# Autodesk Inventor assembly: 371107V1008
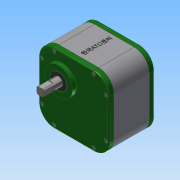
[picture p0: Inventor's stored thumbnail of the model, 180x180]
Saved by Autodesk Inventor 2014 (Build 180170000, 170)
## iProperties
Created: 2017-11
Part Number: 371107V1008
Document SubType Name: Assembly
Designer: NET
Mass: 1902.4 g
Surface Area: 2353.72 cm^2
Volume: 854.265 cm^3
Density: 2.22695 g/cm^3
Author: NET
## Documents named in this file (11)
- C:\Users\NET\Desktop\371107V1008\371107V1008.iam
- C:\Users\NET\Desktop\371107V1008\본체.ipt
- C:\Users\NET\Desktop\371107V1008\뒤커버.ipt
- C:\Users\NET\Desktop\371107V1008\메인축.ipt
- C:\Users\NET\Desktop\371107V1008\베어링 608.ipt
- C:\Users\NET\Desktop\371107V1008\베어링 6003.ipt
- C:\Users\NET\Desktop\371107V1008\볼트 M4.ipt
- C:\Users\NET\Desktop\371107V1008\서브축.ipt
- C:\Users\NET\Desktop\371107V1008\앞커버.ipt
- C:\Users\NET\Desktop\371107V1008\오일실 8 22 7.ipt
- C:\Users\NET\Desktop\371107V1008\오일실 17 32 8.ipt
